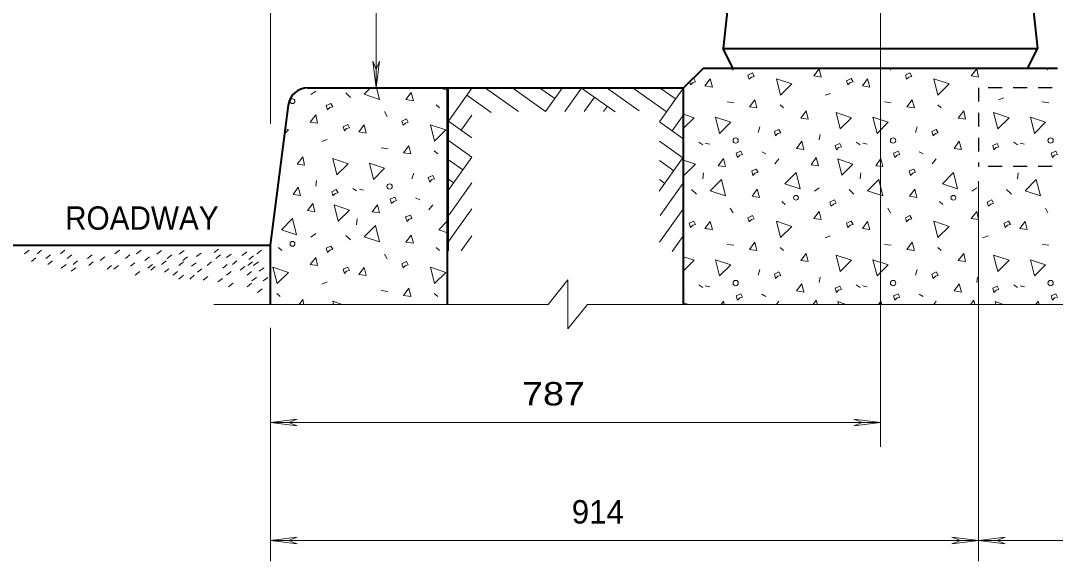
# Model space of a CAD drawing. Extents: x 312583 to 312854, y 144419 to 144597.
# Drawn here: x 312668.37 to 312701.98, y 144446.6 to 144464.15 of the extents above; entities that cross this region are included whole.
import ezdxf

# ---------------------------------------------------------------- set-up
doc = ezdxf.new("R2010")
doc.units = 0
doc.header["$LTSCALE"] = 0.3
doc.linetypes.add('SHORT_DASHED', pattern=[2.7, 1.5, -1.2])
doc.layers.add('1', color=7, linetype='Continuous', lineweight=40)
doc.layers.add('2', color=7, linetype='Continuous', lineweight=13)

msp = doc.modelspace()

# ---------------------------------------------------------------- linework, layer by layer
at = {"layer": '1'}
for p, q in [((312692.4663, 144475.0633), (312691.186, 144463.2489)), ((312700.133, 144475.0633), (312701.4057, 144463.2489)), ((312691.186, 144463.2489), (312701.4057, 144463.2489)), ((312691.508, 144462.6049), (312691.186, 144463.2489)), ((312701.0913, 144462.6049), (312701.4057, 144463.2489)), ((312690.5497, 144462.6049), (312689.9057, 144461.9686)), ((312690.5497, 144462.6049), (312702.0497, 144462.6049)), ((312677.6927, 144461.9686), (312689.9057, 144461.9686)), ((312682.239, 144454.9383), (312682.239, 144461.9686)), ((312689.9057, 144454.9383), (312689.9057, 144461.9686)), ((312667.8563, 144456.8549), (312676.489, 144456.8549))]:
    msp.add_line(p, q, dxfattribs=at)
at = {"layer": '1', "lineweight": 13}
msp.add_line((312696.2997, 144465.1733), (312696.2997, 144450.3076), dxfattribs=at)
at = {"layer": '1', "linetype": 'SHORT_DASHED', "lineweight": 25}
msp.add_line((312702.686, 144459.4156), (312699.489, 144459.4156), dxfattribs=at)
msp.add_lwpolyline([(312702.686, 144461.9686), (312699.489, 144461.9686), (312699.489, 144459.4156)], dxfattribs=at)
at = {"layer": '1'}
msp.add_lwpolyline([(312676.489, 144454.9383), (312676.489, 144456.8549), (312677.064, 144461.4089)], dxfattribs=at)
msp.add_arc((312677.6944, 144461.3284), 0.6389, 90, 172.87498, dxfattribs=at)
at = {"layer": '2'}
for p, q in [((312676.489, 144460.8033), (312676.489, 144496.2769)), ((312679.916, 144461.9686), (312679.916, 144491.9989)), ((312679.8087, 144462.8349), (312679.916, 144462.5589)), ((312679.916, 144461.9686), (312679.8087, 144462.8349)), ((312680.0233, 144462.8349), (312679.916, 144462.5589)), ((312679.916, 144461.9686), (312680.0233, 144462.8349)), ((312691.4773, 144462.6049), (312691.5157, 144462.5359)), ((312696.591, 144462.6049), (312696.6293, 144462.5359)), ((312701.7047, 144462.6049), (312701.743, 144462.5359)), ((312677.8, 144461.7463), (312677.9533, 144461.8613)), ((312678.927, 144461.7999), (312679.0803, 144461.6543)), ((312682.0013, 144461.9686), (312682.239, 144461.8843)), ((312682.2697, 144461.9763), (312682.2697, 144456.6786)), ((312683.0287, 144461.9533), (312682.2697, 144460.8876)), ((312682.86, 144461.7233), (312683.6497, 144461.1636)), ((312683.4733, 144461.9609), (312684.5467, 144461.2019)), ((312684.355, 144461.9609), (312685.4207, 144461.2019)), ((312685.2367, 144461.9609), (312685.7197, 144461.6159)), ((312685.4207, 144461.2019), (312685.965, 144461.9609)), ((312686.0493, 144461.2019), (312686.5937, 144461.9609)), ((312686.5937, 144461.9609), (312687.6823, 144461.1866)), ((312687.4217, 144461.9609), (312688.4643, 144461.2173)), ((312688.265, 144461.9609), (312689.3383, 144461.2019)), ((312689.8827, 144461.9379), (312689.1237, 144460.8646)), ((312689.1467, 144461.9609), (312689.6297, 144461.6159)), ((312694.682, 144461.7846), (312694.5057, 144461.7233)), ((312681.8633, 144461.4166), (312681.9707, 144461.3169)), ((312686.678, 144461.2019), (312687.0077, 144461.6619)), ((312691.5387, 144461.4779), (312691.3163, 144461.5163)), ((312693.0413, 144461.4166), (312693.1563, 144461.3169)), ((312696.6523, 144461.4779), (312696.43, 144461.5163)), ((312698.1627, 144461.4166), (312698.2777, 144461.3169)), ((312700.3093, 144461.6466), (312700.133, 144461.5776)), ((312701.7737, 144461.4779), (312701.5513, 144461.5163)), ((312680.1843, 144461.1943), (312680.2763, 144461.0409)), ((312683.0287, 144461.0793), (312682.6837, 144460.5886)), ((312687.3067, 144461.2019), (312687.4293, 144461.3706)), ((312689.8827, 144461.0563), (312689.5377, 144460.5656)), ((312682.2697, 144460.8876), (312683.0287, 144460.3433)), ((312689.1237, 144460.8646), (312689.8827, 144460.3203)), ((312692.382, 144460.6959), (312692.3283, 144460.5119)), ((312694.3447, 144460.4506), (312694.314, 144460.2743)), ((312697.4957, 144460.6959), (312697.442, 144460.5119)), ((312678.3213, 144460.2896), (312678.1527, 144460.2283)), ((312682.2697, 144460.2589), (312683.0287, 144459.7146)), ((312689.1237, 144460.2359), (312689.8827, 144459.6993)), ((312690.3963, 144460.1976), (312690.5267, 144460.1133)), ((312690.611, 144460.1746), (312690.7567, 144460.1363)), ((312695.5177, 144460.1976), (312695.6403, 144460.1133)), ((312695.7323, 144460.1746), (312695.8703, 144460.1363)), ((312700.6313, 144460.1976), (312700.754, 144460.1133)), ((312700.846, 144460.1746), (312700.984, 144460.1363)), ((312680.2993, 144459.9829), (312680.077, 144460.0213)), ((312681.802, 144459.9216), (312681.917, 144459.8219)), ((312683.0287, 144459.7146), (312682.2543, 144458.6336)), ((312689.8827, 144459.6993), (312689.1083, 144458.6106)), ((312692.4433, 144459.8909), (312692.5737, 144459.8219)), ((312697.557, 144459.8909), (312697.6873, 144459.8219)), ((312682.2697, 144459.6303), (312682.7373, 144459.3006)), ((312689.1237, 144459.6073), (312689.5913, 144459.2776)), ((312693.003, 144459.6609), (312692.8727, 144459.4999)), ((312698.1167, 144459.6609), (312697.9863, 144459.4999)), ((312681.1427, 144459.2009), (312681.0813, 144459.0169)), ((312689.9057, 144459.1933), (312689.9287, 144459.1319)), ((312690.5497, 144459.2086), (312690.5267, 144459.0093)), ((312695.6633, 144459.2086), (312695.6403, 144459.0093)), ((312700.777, 144459.2086), (312700.754, 144459.0093)), ((312677.984, 144458.9556), (312677.961, 144458.7793)), ((312679.157, 144458.7026), (312679.2797, 144458.6259)), ((312682.2697, 144459.0016), (312682.4383, 144458.8866)), ((312683.0287, 144458.8866), (312682.2927, 144457.8439)), ((312689.1237, 144458.9863), (312689.2923, 144458.8636)), ((312689.8827, 144458.8636), (312689.1467, 144457.8209)), ((312694.1607, 144458.6106), (312694.3063, 144458.7256)), ((312699.2743, 144458.6106), (312699.4277, 144458.7256)), ((312699.489, 144458.9326), (312699.489, 144446.5969)), ((312679.3717, 144458.6796), (312679.5097, 144458.6413)), ((312681.1963, 144458.3959), (312681.3343, 144458.3269)), ((312690.1663, 144458.6643), (312690.3273, 144458.5186)), ((312695.2877, 144458.6643), (312695.441, 144458.5186)), ((312700.4013, 144458.6643), (312700.5547, 144458.5186)), ((312681.7637, 144458.1659), (312681.6257, 144458.0049)), ((312683.0287, 144458.0433), (312682.2697, 144456.9776)), ((312689.8827, 144458.0203), (312689.1237, 144456.9546)), ((312691.4237, 144458.0586), (312691.5157, 144457.9129)), ((312693.1027, 144458.2809), (312693.21, 144458.1813)), ((312696.5373, 144458.0586), (312696.6293, 144457.9129)), ((312698.2163, 144458.2809), (312698.3237, 144458.1813)), ((312701.6587, 144458.0586), (312701.743, 144457.9129)), ((312679.3027, 144457.7136), (312679.2797, 144457.5143)), ((312677.8, 144457.1156), (312677.9533, 144457.2383)), ((312678.927, 144457.1693), (312679.0803, 144457.0313)), ((312683.0287, 144457.1616), (312682.6837, 144456.6786)), ((312689.8827, 144457.1386), (312689.5377, 144456.6556)), ((312694.682, 144457.1616), (312694.5057, 144457.0926)), ((312699.7957, 144457.1616), (312699.6193, 144457.0926)), ((312668.4927, 144456.5789), (312668.646, 144456.6939)), ((312668.899, 144456.5789), (312669.0447, 144456.6939)), ((312669.658, 144456.5789), (312669.8037, 144456.6939)), ((312671.429, 144456.5789), (312671.5747, 144456.6939)), ((312672.1343, 144456.5789), (312672.2877, 144456.6939)), ((312672.7937, 144456.5713), (312672.947, 144456.6863)), ((312673.522, 144456.5713), (312673.6753, 144456.6863)), ((312674.649, 144456.6173), (312674.7947, 144456.7323)), ((312676.0443, 144456.5789), (312676.19, 144456.6939)), ((312676.742, 144456.7859), (312676.8493, 144456.6863)), ((312681.8633, 144456.7859), (312681.9707, 144456.6863)), ((312691.5387, 144456.8549), (312691.3163, 144456.8856)), ((312693.0413, 144456.7859), (312693.1563, 144456.6863)), ((312696.6523, 144456.8549), (312696.43, 144456.8856)), ((312698.1627, 144456.7859), (312698.2777, 144456.6863)), ((312701.7737, 144456.8549), (312701.5513, 144456.8856)), ((312668.715, 144456.3259), (312668.8607, 144456.4486)), ((312669.1827, 144456.4256), (312669.336, 144456.5406)), ((312669.2517, 144456.2339), (312669.3973, 144456.3489)), ((312669.8803, 144456.4256), (312670.026, 144456.5406)), ((312670.072, 144456.2339), (312670.2177, 144456.3489)), ((312670.5397, 144456.4256), (312670.693, 144456.5406)), ((312670.9537, 144456.3643), (312671.0993, 144456.4793)), ((312671.774, 144456.4256), (312671.9197, 144456.5406)), ((312672.4027, 144456.3643), (312672.556, 144456.4793)), ((312672.9393, 144456.2339), (312673.0927, 144456.3489)), ((312673.131, 144456.4256), (312673.2767, 144456.5406)), ((312673.637, 144456.3643), (312673.7827, 144456.4793)), ((312674.0817, 144456.4869), (312674.2273, 144456.6019)), ((312674.7103, 144456.4256), (312674.856, 144456.5406)), ((312675.0553, 144456.4563), (312675.2087, 144456.5713)), ((312675.247, 144456.2339), (312675.3927, 144456.3489)), ((312675.569, 144456.5253), (312675.7147, 144456.6479)), ((312675.7837, 144456.3949), (312675.9293, 144456.5099)), ((312680.1843, 144456.5636), (312680.2763, 144456.4179)), ((312669.6887, 144456.1113), (312669.842, 144456.2263)), ((312670.0107, 144456.0116), (312670.1563, 144456.1266)), ((312670.578, 144456.2033), (312670.7237, 144456.3183)), ((312671.176, 144456.0806), (312671.3217, 144456.1956)), ((312671.3983, 144456.0806), (312671.544, 144456.1956)), ((312671.935, 144456.1726), (312672.0807, 144456.2876)), ((312672.0883, 144455.8889), (312672.2417, 144456.0039)), ((312672.5023, 144456.1113), (312672.648, 144456.2263)), ((312672.5943, 144456.0423), (312672.74, 144456.1649)), ((312673.039, 144455.9809), (312673.1847, 144456.0959)), ((312673.3227, 144455.8889), (312673.4683, 144456.0039)), ((312673.5067, 144456.2033), (312673.66, 144456.3183)), ((312673.9207, 144456.1726), (312674.0663, 144456.2876)), ((312674.1123, 144455.9809), (312674.258, 144456.0959)), ((312674.4267, 144456.2033), (312674.5723, 144456.3183)), ((312674.9327, 144456.1113), (312675.0783, 144456.2263)), ((312675.0553, 144455.8889), (312675.2087, 144456.0039)), ((312675.5, 144456.0423), (312675.6457, 144456.1649)), ((312675.7223, 144455.8889), (312675.868, 144456.0039)), ((312675.753, 144456.2033), (312675.8987, 144456.3183)), ((312675.937, 144456.2033), (312676.0903, 144456.3183)), ((312676.121, 144456.0116), (312676.2743, 144456.1266)), ((312692.382, 144456.0653), (312692.3283, 144455.8889)), ((312697.4957, 144456.0653), (312697.442, 144455.8889)), ((312673.5067, 144455.7586), (312673.66, 144455.8813)), ((312673.8593, 144455.7586), (312674.005, 144455.8813)), ((312674.2963, 144455.7279), (312674.4497, 144455.8429)), ((312674.7717, 144455.6666), (312674.925, 144455.7816)), ((312675.8757, 144455.6973), (312676.029, 144455.8123)), ((312676.2437, 144455.6973), (312676.397, 144455.8123)), ((312678.3213, 144455.6666), (312678.1527, 144455.5976)), ((312694.3447, 144455.8199), (312694.314, 144455.6436)), ((312699.4583, 144455.8199), (312699.4353, 144455.6436)), ((312675.1167, 144455.5056), (312675.27, 144455.6283)), ((312675.7223, 144455.5056), (312675.868, 144455.6283)), ((312676.0673, 144455.3216), (312676.213, 144455.4366)), ((312680.2993, 144455.3599), (312680.077, 144455.3906)), ((312690.3963, 144455.5746), (312690.5267, 144455.4903)), ((312690.611, 144455.5439), (312690.7567, 144455.5056)), ((312695.5177, 144455.5746), (312695.6403, 144455.4903)), ((312695.7323, 144455.5439), (312695.8703, 144455.5056)), ((312700.6313, 144455.5746), (312700.754, 144455.4903)), ((312700.846, 144455.5439), (312700.984, 144455.5056)), ((312676.6883, 144455.2909), (312676.8033, 144455.1913)), ((312681.802, 144455.2909), (312681.917, 144455.1913)), ((312690.0667, 144454.9383), (312689.9057, 144454.9919)), ((312692.4433, 144455.2679), (312692.5737, 144455.1913)), ((312693.003, 144455.0379), (312692.9263, 144454.9383)), ((312697.557, 144455.2679), (312697.6873, 144455.1913)), ((312698.1167, 144455.0379), (312698.04, 144454.9383)), ((312685.505, 144454.9383), (312674.6413, 144454.9383)), ((312706.734, 144454.9383), (312686.7853, 144454.9383)), ((312676.489, 144454.1716), (312676.489, 144446.5969)), ((312676.489, 144451.1049), (312677.3553, 144451.2123)), ((312696.2997, 144451.1049), (312676.489, 144451.1049)), ((312676.489, 144451.1049), (312677.3553, 144450.9976)), ((312677.3553, 144451.2123), (312677.0793, 144451.1049)), ((312677.3553, 144450.9976), (312677.0793, 144451.1049)), ((312695.4333, 144451.2123), (312695.7093, 144451.1049)), ((312696.2997, 144451.1049), (312695.4333, 144451.2123)), ((312695.4333, 144450.9976), (312695.7093, 144451.1049)), ((312696.2997, 144451.1049), (312695.4333, 144450.9976)), ((312676.489, 144447.2716), (312677.3553, 144447.3789)), ((312676.489, 144447.2716), (312677.3553, 144447.1643)), ((312677.3553, 144447.3789), (312677.0793, 144447.2716)), ((312677.3553, 144447.1643), (312677.0793, 144447.2716)), ((312698.6227, 144447.3789), (312698.8987, 144447.2716)), ((312699.489, 144447.2716), (312698.6227, 144447.3789)), ((312698.6227, 144447.1643), (312698.8987, 144447.2716)), ((312699.489, 144447.2716), (312698.6227, 144447.1643)), ((312699.489, 144447.2716), (312700.3553, 144447.3789)), ((312699.489, 144447.2716), (312700.3553, 144447.1643)), ((312700.3553, 144447.3789), (312700.0793, 144447.2716)), ((312700.3553, 144447.1643), (312700.0793, 144447.2716))]:
    msp.add_line(p, q, dxfattribs=at)
for points in [[(312692.1137, 144462.3136), (312692.198, 144462.3366), (312692.1443, 144462.4516), (312691.991, 144462.3826), (312692.037, 144462.2446)], [(312694.1377, 144462.3519), (312694.3753, 144462.3136), (312694.3063, 144462.5819)], [(312697.2273, 144462.3136), (312697.3193, 144462.3366), (312697.258, 144462.4516), (312697.1123, 144462.3826), (312697.1507, 144462.2446)], [(312699.2513, 144462.3519), (312699.489, 144462.3136), (312699.4277, 144462.5819)], [(312690.5957, 144462.0299), (312690.841, 144461.9916), (312690.772, 144462.2599)], [(312693.0567, 144461.7309), (312693.4247, 144462.0989), (312692.9263, 144462.2599)], [(312695.3183, 144462.1373), (312695.4103, 144462.1603), (312695.349, 144462.2676), (312695.2033, 144462.1986), (312695.2417, 144462.0606)], [(312695.717, 144462.0299), (312695.9547, 144461.9916), (312695.8857, 144462.2599)], [(312698.1703, 144461.7309), (312698.5383, 144462.0989), (312698.04, 144462.2599)], [(312680.882, 144461.5853), (312681.1273, 144461.5469), (312681.0583, 144461.8153)], [(312678.4133, 144461.3246), (312678.5053, 144461.3476), (312678.444, 144461.4549), (312678.2983, 144461.3936), (312678.3367, 144461.2479)], [(312692.0447, 144461.3476), (312692.2823, 144461.3169), (312692.221, 144461.5776)], [(312697.1583, 144461.3476), (312697.4037, 144461.3169), (312697.3347, 144461.5776)], [(312677.777, 144460.8569), (312678.0147, 144460.8186), (312677.9533, 144461.0869)], [(312693.716, 144460.9873), (312693.9537, 144460.9489), (312693.8847, 144461.2173)], [(312694.9963, 144460.6346), (312695.3643, 144460.9949), (312694.866, 144461.1636)], [(312698.8297, 144460.9873), (312699.0673, 144460.9489), (312699.006, 144461.2173)], [(312700.1177, 144460.6346), (312700.478, 144460.9949), (312699.9797, 144461.1636)], [(312678.9577, 144460.6423), (312679.0497, 144460.6653), (312678.996, 144460.7726), (312678.8427, 144460.7036), (312678.8887, 144460.5656)], [(312679.3563, 144460.5349), (312679.594, 144460.4966), (312679.5327, 144460.7649)], [(312680.8667, 144460.8186), (312680.9587, 144460.8493), (312680.905, 144460.9566), (312680.7517, 144460.8876), (312680.79, 144460.7496)], [(312681.8173, 144460.2359), (312682.1777, 144460.6039), (312681.687, 144460.7649)], [(312691.071, 144460.4813), (312691.439, 144460.8493), (312690.9407, 144461.0103)], [(312696.1923, 144460.4813), (312696.5527, 144460.8493), (312696.0543, 144461.0103)], [(312701.306, 144460.4813), (312701.6663, 144460.8493), (312701.1757, 144461.0103)], [(312692.9723, 144460.4813), (312693.0643, 144460.5043), (312693.003, 144460.6116), (312692.8573, 144460.5503), (312692.8957, 144460.4046)], [(312698.086, 144460.4813), (312698.178, 144460.5043), (312698.1167, 144460.6116), (312697.971, 144460.5503), (312698.0093, 144460.4046)], [(312680.8053, 144459.8526), (312681.043, 144459.8219), (312680.974, 144460.0826)], [(312693.5703, 144459.9983), (312693.8157, 144459.9676), (312693.7467, 144460.2359)], [(312694.9427, 144460.0289), (312695.0347, 144460.0519), (312694.981, 144460.1593), (312694.8277, 144460.0903), (312694.8737, 144459.9523)], [(312698.6917, 144459.9983), (312698.9293, 144459.9676), (312698.8603, 144460.2359)], [(312700.064, 144460.0289), (312700.1483, 144460.0519), (312700.0947, 144460.1593), (312699.949, 144460.0903), (312699.9873, 144459.9523)], [(312677.3553, 144459.4923), (312677.593, 144459.4539), (312677.5317, 144459.7223)], [(312691.7303, 144459.7759), (312691.8223, 144459.8066), (312691.761, 144459.9139), (312691.6153, 144459.8449), (312691.6537, 144459.7069)], [(312694.0457, 144459.4693), (312694.2833, 144459.4386), (312694.2143, 144459.7069)], [(312696.844, 144459.7759), (312696.936, 144459.8066), (312696.8823, 144459.9139), (312696.729, 144459.8449), (312696.7673, 144459.7069)], [(312701.9577, 144459.7759), (312702.0497, 144459.8066), (312701.996, 144459.9139), (312701.8427, 144459.8449), (312701.8887, 144459.7069)], [(312678.6433, 144459.1396), (312679.0037, 144459.4999), (312678.513, 144459.6686)], [(312679.8317, 144458.9939), (312680.192, 144459.3543), (312679.7013, 144459.5229)], [(312691.025, 144459.4386), (312691.2703, 144459.4079), (312691.2013, 144459.6686)], [(312695.0423, 144459.1319), (312695.4027, 144459.4923), (312694.912, 144459.6609)], [(312696.1463, 144459.4386), (312696.384, 144459.4079), (312696.315, 144459.6686)], [(312681.7253, 144458.9863), (312681.8173, 144459.0093), (312681.7637, 144459.1166), (312681.6103, 144459.0553), (312681.6563, 144458.9096)], [(312692.2363, 144459.2009), (312692.3283, 144459.2239), (312692.267, 144459.3313), (312692.1213, 144459.2699), (312692.1597, 144459.1243)], [(312693.5627, 144459.2163), (312693.1947, 144458.8483), (312693.693, 144458.6873)], [(312697.35, 144459.2009), (312697.442, 144459.2239), (312697.3807, 144459.3313), (312697.235, 144459.2699), (312697.2733, 144459.1243)], [(312698.6763, 144459.2163), (312698.316, 144458.8483), (312698.8067, 144458.6873)], [(312677.2173, 144458.5033), (312677.455, 144458.4726), (312677.386, 144458.7409)], [(312691.1323, 144458.9939), (312690.7643, 144458.6259), (312691.2627, 144458.4649)], [(312696.246, 144458.9939), (312695.8857, 144458.6259), (312696.3763, 144458.4649)], [(312701.3597, 144458.9939), (312700.9993, 144458.6259), (312701.4977, 144458.4649)], [(312678.5897, 144458.5339), (312678.6817, 144458.5569), (312678.6203, 144458.6643), (312678.4747, 144458.5953), (312678.513, 144458.4573)], [(312680.491, 144458.2809), (312680.5753, 144458.3116), (312680.5217, 144458.4189), (312680.376, 144458.3499), (312680.4143, 144458.2119)], [(312692.129, 144458.4496), (312692.3667, 144458.4113), (312692.2977, 144458.6796)], [(312697.2427, 144458.4496), (312697.4803, 144458.4113), (312697.419, 144458.6796)], [(312677.685, 144457.9819), (312677.9303, 144457.9436), (312677.8613, 144458.2119)], [(312678.6817, 144457.6369), (312679.0497, 144457.9973), (312678.5513, 144458.1659)], [(312679.7857, 144457.9436), (312680.0233, 144457.9129), (312679.962, 144458.1736)], [(312694.774, 144458.1889), (312694.866, 144458.2196), (312694.8047, 144458.3269), (312694.659, 144458.2579), (312694.6973, 144458.1199)], [(312699.8877, 144458.1889), (312699.9797, 144458.2196), (312699.9183, 144458.3269), (312699.7727, 144458.2579), (312699.811, 144458.1199)], [(312677.202, 144457.7213), (312676.8417, 144457.3533), (312677.3323, 144457.1923)], [(312680.9893, 144457.7059), (312681.0813, 144457.7289), (312681.0277, 144457.8363), (312680.8743, 144457.7749), (312680.9203, 144457.6293)], [(312692.1137, 144457.6906), (312692.198, 144457.7136), (312692.1443, 144457.8209), (312691.991, 144457.7519), (312692.037, 144457.6139)], [(312694.1377, 144457.7213), (312694.3753, 144457.6906), (312694.3063, 144457.9513)], [(312697.2273, 144457.6906), (312697.3193, 144457.7136), (312697.258, 144457.8209), (312697.1123, 144457.7519), (312697.1507, 144457.6139)], [(312699.2513, 144457.7213), (312699.489, 144457.6906), (312699.4277, 144457.9513)], [(312679.893, 144457.4989), (312679.525, 144457.1309), (312680.0233, 144456.9699)], [(312690.2047, 144457.5066), (312690.289, 144457.5296), (312690.2353, 144457.6369), (312690.0897, 144457.5756), (312690.128, 144457.4299)], [(312690.5957, 144457.3993), (312690.841, 144457.3686), (312690.772, 144457.6293)], [(312693.0567, 144457.1079), (312693.4247, 144457.4683), (312692.9263, 144457.6369)], [(312695.3183, 144457.5066), (312695.4103, 144457.5296), (312695.349, 144457.6369), (312695.2033, 144457.5756), (312695.2417, 144457.4299)], [(312695.717, 144457.3993), (312695.9547, 144457.3686), (312695.8857, 144457.6293)], [(312698.1703, 144457.1079), (312698.5383, 144457.4683), (312698.04, 144457.6369)], [(312700.432, 144457.5066), (312700.524, 144457.5296), (312700.4627, 144457.6369), (312700.317, 144457.5756), (312700.3553, 144457.4299)], [(312700.8307, 144457.3993), (312701.0683, 144457.3686), (312700.9993, 144457.6293)], [(312680.882, 144456.9546), (312681.1273, 144456.9239), (312681.0583, 144457.1846)], [(312678.4133, 144456.7016), (312678.5053, 144456.7246), (312678.444, 144456.8319), (312678.2983, 144456.7629), (312678.3367, 144456.6249)], [(312692.0447, 144456.7169), (312692.2823, 144456.6863), (312692.221, 144456.9546)], [(312697.1583, 144456.7169), (312697.4037, 144456.6863), (312697.3347, 144456.9546)], [(312677.777, 144456.2263), (312678.0147, 144456.1956), (312677.9533, 144456.4563)], [(312691.071, 144455.8583), (312691.439, 144456.2186), (312690.9407, 144456.3873)], [(312693.716, 144456.3566), (312693.9537, 144456.3259), (312693.8847, 144456.5866)], [(312694.9963, 144456.0039), (312695.3643, 144456.3719), (312694.866, 144456.5329)], [(312696.1923, 144455.8583), (312696.5527, 144456.2186), (312696.0543, 144456.3873)], [(312698.8297, 144456.3566), (312699.0673, 144456.3259), (312699.006, 144456.5866)], [(312700.1177, 144456.0039), (312700.478, 144456.3719), (312699.9797, 144456.5329)], [(312701.306, 144455.8583), (312701.6663, 144456.2186), (312701.1757, 144456.3873)], [(312676.696, 144455.6129), (312677.064, 144455.9733), (312676.5657, 144456.1419)], [(312678.9577, 144456.0116), (312679.0497, 144456.0346), (312678.996, 144456.1419), (312678.8427, 144456.0806), (312678.8887, 144455.9349)], [(312679.3563, 144455.9043), (312679.594, 144455.8736), (312679.5327, 144456.1343)], [(312680.8667, 144456.1956), (312680.9587, 144456.2186), (312680.905, 144456.3259), (312680.7517, 144456.2569), (312680.79, 144456.1189)], [(312681.8173, 144455.6129), (312682.1777, 144455.9733), (312681.687, 144456.1419)], [(312692.9723, 144455.8506), (312693.0643, 144455.8736), (312693.003, 144455.9886), (312692.8573, 144455.9196), (312692.8957, 144455.7816)], [(312698.086, 144455.8506), (312698.178, 144455.8736), (312698.1167, 144455.9886), (312697.971, 144455.9196), (312698.0093, 144455.7816)], [(312680.8053, 144455.2296), (312681.043, 144455.1913), (312680.974, 144455.4596)], [(312693.5703, 144455.3753), (312693.8157, 144455.3369), (312693.7467, 144455.6053)], [(312694.9427, 144455.3983), (312695.0347, 144455.4213), (312694.981, 144455.5286), (312694.8277, 144455.4673), (312694.8737, 144455.3216)], [(312698.6917, 144455.3753), (312698.9293, 144455.3369), (312698.8603, 144455.6053)], [(312700.064, 144455.3983), (312700.1483, 144455.4213), (312700.0947, 144455.5286), (312699.949, 144455.4673), (312699.9873, 144455.3216)], [(312691.7303, 144455.1529), (312691.8223, 144455.1759), (312691.761, 144455.2833), (312691.6153, 144455.2143), (312691.6537, 144455.0763)], [(312696.844, 144455.1529), (312696.936, 144455.1759), (312696.8823, 144455.2833), (312696.729, 144455.2143), (312696.7673, 144455.0763)], [(312701.9577, 144455.1529), (312702.0497, 144455.1759), (312701.996, 144455.2833), (312701.8427, 144455.2143), (312701.8887, 144455.0763)]]:
    msp.add_lwpolyline(points, close=True, dxfattribs=at)
for points in [[(312690.0973, 144462.1603), (312690.128, 144462.0606), (312690.2047, 144462.1373)], [(312690.2047, 144462.1373), (312690.289, 144462.1603), (312690.2353, 144462.2676), (312690.1893, 144462.2446)], [(312677.294, 144461.8306), (312677.3323, 144461.8153), (312677.3323, 144461.8383)], [(312679.732, 144461.9686), (312679.525, 144461.7616), (312680.0233, 144461.5929), (312679.9313, 144461.9686)], [(312689.9057, 144460.6576), (312690.2507, 144460.9949), (312689.9057, 144461.1099)], [(312676.949, 144460.4813), (312677.064, 144460.6039), (312676.9643, 144460.6346)], [(312689.9057, 144460.0443), (312689.921, 144460.0519), (312689.9057, 144460.0749)], [(312689.9287, 144459.1319), (312690.289, 144459.4923), (312689.9057, 144459.6226)], [(312682.239, 144457.6446), (312681.9553, 144457.3533), (312682.239, 144457.2613)], [(312689.9057, 144456.0269), (312690.2507, 144456.3719), (312689.9057, 144456.4793)], [(312686.7853, 144454.9383), (312686.149, 144454.1409), (312686.149, 144455.7356), (312685.505, 144454.9383)], [(312689.9057, 144455.4213), (312689.921, 144455.4213), (312689.9057, 144455.4443)], [(312677.57, 144454.9383), (312677.5317, 144455.0916), (312677.4167, 144454.9383)], [(312678.812, 144454.9383), (312678.513, 144455.0379), (312678.536, 144454.9383)], [(312691.2243, 144454.9383), (312691.2013, 144455.0456), (312691.1247, 144454.9383)], [(312694.2527, 144454.9383), (312694.2143, 144455.0763), (312694.1147, 144454.9383)], [(312695.1803, 144454.9383), (312694.912, 144455.0303), (312694.935, 144454.9383)], [(312696.3457, 144454.9383), (312696.315, 144455.0456), (312696.2383, 144454.9383)], [(312699.3663, 144454.9383), (312699.3357, 144455.0763), (312699.2283, 144454.9383)], [(312700.294, 144454.9383), (312700.0257, 144455.0303), (312700.0487, 144454.9383)], [(312701.4593, 144454.9383), (312701.4287, 144455.0456), (312701.352, 144454.9383)], [(312730.1557, 144447.2716), (312699.489, 144447.2716), (312676.489, 144447.2716)]]:
    msp.add_lwpolyline(points, dxfattribs=at)
for centre, radius in [((312677.1988, 144461.5316), 0.0784), ((312691.5974, 144460.257), 0.0865), ((312696.713, 144460.257), 0.0865), ((312701.8286, 144460.257), 0.0865), ((312680.3556, 144458.7627), 0.0865), ((312693.5563, 144458.3979), 0.0784), ((312698.6719, 144458.3979), 0.0784), ((312677.1988, 144456.9035), 0.0784), ((312691.5974, 144455.6289), 0.0865), ((312696.713, 144455.6289), 0.0865), ((312701.8286, 144455.6289), 0.0865)]:
    msp.add_circle(centre, radius, dxfattribs=at)

# ---------------------------------------------------------------- texts
for s, width, p in [('ROADWAY', 0.95, (312669.8104, 144457.36)), ('787 ', 1.2, (312684.6599, 144451.656))]:
    msp.add_text(s, height=0.76, dxfattribs=dict(at, width=width)).set_placement(p)
msp.add_text('914', height=0.76, dxfattribs=at).set_placement((312686.2712, 144447.8227))

doc.saveas('drawing.dxf')
